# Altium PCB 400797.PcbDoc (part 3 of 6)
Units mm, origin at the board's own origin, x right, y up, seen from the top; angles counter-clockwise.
Board outline 155 x 63.5 mm, 4 copper layers (Top Layer, Mid-Layer 1, Mid-Layer 2, Bottom Layer), stack 1.514 mm thick; 317 components, 286 nets, 1519 pads, 2174 vias.
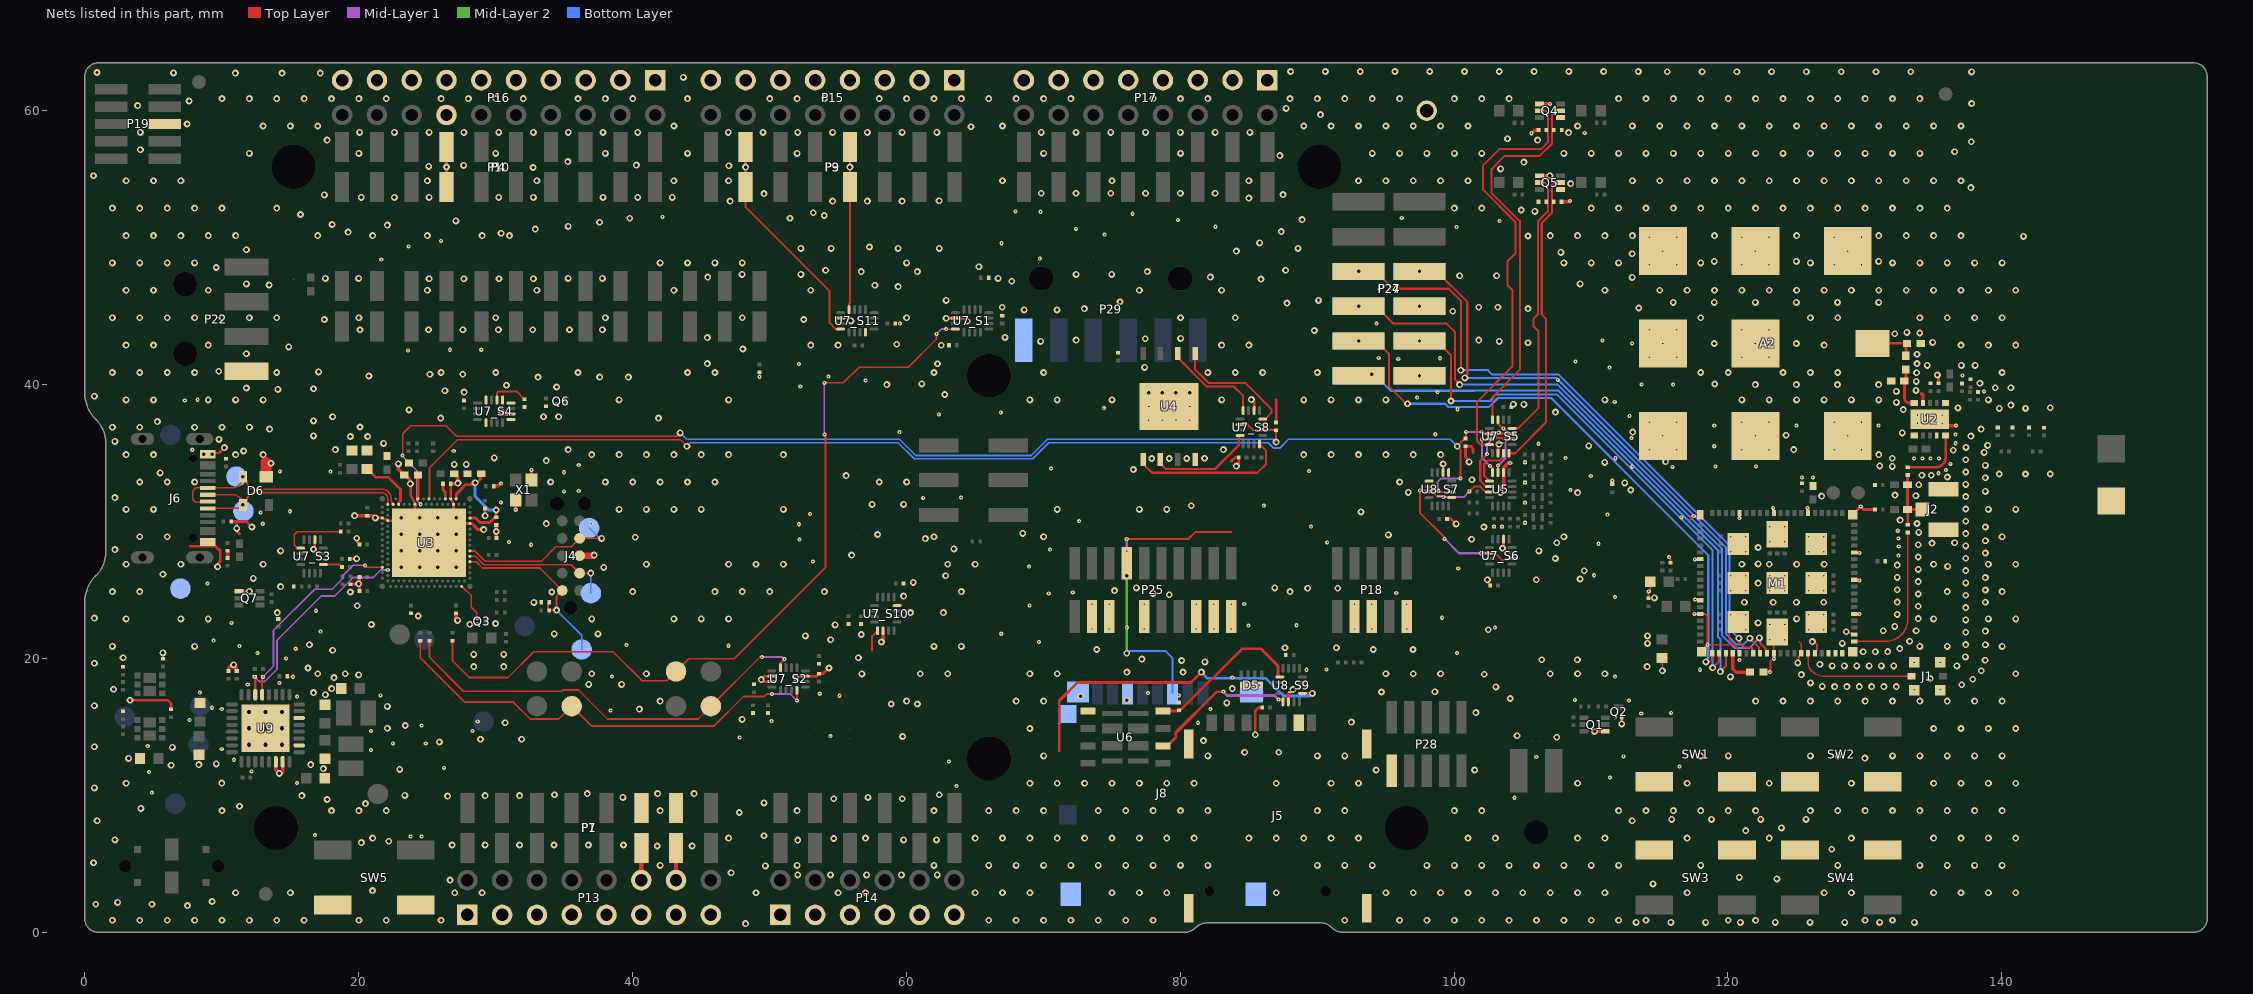
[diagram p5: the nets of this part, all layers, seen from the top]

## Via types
v1: diameter 0.5, hole 0.25, Top Layer to Bottom Layer, tented both sides, 1623 vias
v2: diameter 0.3, hole 0.1, Top Layer to Mid-Layer 1, tented top, 445 vias
v3: diameter 0.3, hole 0.1, Top Layer to Mid-Layer 1, tented both sides, 97 vias
v4: diameter 0.61, hole 0.305, Top Layer to Bottom Layer, tented both sides, 9 vias

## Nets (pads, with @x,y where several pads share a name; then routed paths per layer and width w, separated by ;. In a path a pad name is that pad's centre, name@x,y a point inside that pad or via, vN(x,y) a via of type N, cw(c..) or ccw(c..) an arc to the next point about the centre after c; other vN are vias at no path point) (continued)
COM.CH2_S2: R16.2 TP10.1 U7_S2.4 | length 31.8
  Top Layer w0.125: R16.2@25.175,21.299 25.175,20.088 27.651,17.613 34.83,17.613 34.915,17.698 36.052,17.698 36.748,17.002 36.748,16.999 38.174,15.573 44.782,15.573 TP10.1@45.72,16.51 49.31,20.1 v2(49.45,20.1)
  Top Layer w0.15: U7_S2.4@50.8,19.325 50.8,19.65 v2(51.1,19.95)
  Mid-Layer 1 w0.15: v2(49.45,20.1) 50.95,20.1 v2(51.1,19.95)
COM.CH2_S11: P3.4 P9.4 U7_S11.4 | length 15.4
  Top Layer w0.15: U7_S11.4@55.818,45.475 55.818,45.875 55.881,45.938 P3.4@55.88,54.416 P3.4@55.88,57.346
  Bottom Layer w0.15: P9.4@55.88,53.824 P9.4@55.88,54.416 v1(55.88,55.881) P9.4@55.88,57.346
COM.CH3_S1: R12.2 TP7.1 U7_S1.8 | length 59.3
  Top Layer w0.125: R12.2@26.85,21.299 26.85,19.827 28.065,18.613 30.903,18.613 32.778,20.488 38.573,20.488 40.698,18.363 42.492,18.363 TP7.1@43.18,19.05 44.118,19.988 47.423,19.988 54.1,26.664 54.1,36.263 v2(54.013,36.35) ; v2(54.013,40.125) 55.4,40.125 56.55,41.275 60.15,41.275 62.2,43.325 v2(62.2,43.7) ; v2(62.9,44.052) 62.902,44.05 U7_S1.8@63.575,44.05
  Mid-Layer 1 w0.125: v2(54.013,36.35) v2(54.013,40.125) ; v2@62.175,43.675 v2(62.2,43.7) 62.552,44.052 v2(62.9,44.052)
COM.CH3_S4: U7_S4.8
COM.CH3_S11: P3.7 P9.7 U7_S11.8 | length 19.9
  Top Layer w0.15: P3.7@48.26,57.346 48.26,52.962 54.393,46.829 54.393,44.504 54.846,44.05 U7_S11.8@55.193,44.05
  Bottom Layer w0.15: P9.7@48.26,53.849 P9.7@48.26,54.416 P9.7@48.26,57.346
  other v1: 48.26,55.881
COM.CH4_S2: R15.2 TP6.1 U7_S2.12 | length 33.5
  Top Layer w0.125: R15.2@24.5,21.299 24.5,20.056 27.744,16.813 31.302,16.813 32.542,15.573 34.622,15.573 TP6.1@35.56,16.51 36.998,15.073 45.962,15.073 48.107,17.218 49.621,17.218 49.804,17.4 v2(50.2,17.4)
  Top Layer w0.15: v2(52,16.925) U7_S2.12@52,17.675
  Mid-Layer 1 w0.125: v2(50.2,17.4) 51.525,17.4 v2(52,16.925)
COM.CH4_S4: U7_S4.12
COM.CH4_S10: U7_S10.12
COM.CH4_S11: U7_S11.12
D_N: D6.2 J6.A7 J6.B7 TP19.1 U3.B4 | length 18.2
  Top Layer w0.1: J6.A7@8.985,31.455 cw(c8.935,31.455) 8.935,31.405 8.2,31.405 cw(c8.2,31.705) 7.9,31.705 7.9,32.161 cw(c8.194,32.161) 8.194,32.455 J6.B7@8.985,32.455 10.738,32.455 ccw(c10.738,33.264) v1(11.547,33.259) ; D6.2@11.547,33.264 cw(c10.738,33.264) v1(11.547,33.259) ; U3.B4@22.525,31.264 22.525,31.314 22.375,31.464 22.375,31.664 ccw(c21.675,31.664) 21.675,32.364 12.397,32.364 cw(c12.397,32.914) 11.847,32.914 ccw(c11.497,32.914) v1(11.547,33.259)
D_P: D6.3 J6.A6 J6.B6 TP20.1 U3.B2 | length 17.4
  Top Layer w0.1: J6.B6@8.985,30.955 11.288,30.955 ccw(c11.288,31.214) 11.547,31.214 ccw(c10.805,31.214) D6.3@11.547,31.217 ; J6.A6@8.985,31.955 10.805,31.955 cw(c10.805,31.214) D6.3@11.547,31.217 ; U3.B2@22.125,31.264 22.125,31.664 ccw(c21.675,31.664) 21.675,32.114 12.397,32.114 ccw(c12.397,31.564) 11.847,31.564 cw(c11.497,31.564) D6.3@11.547,31.217
  other v1: 11.547,31.209
DBG_CMD: J8.3 P25.8 SB11.1 | length 20.5
  Top Layer w0.15: v2(76.095,28.72) 80.595,28.72 81.125,29.25 SB11.1@83.65,29.25 83.688,29.25
  Mid-Layer 1 w0.15: v2(76.095,27.85) v2(76.095,28.72)
  Mid-Layer 2 w0.15: v1(76.095,20.375) v1(76.095,26.05)
  Bottom Layer w0.15: v1(76.095,20.375) 76.27,20.55 78.9,20.55 79.45,20 J8.3@79.45,17.47
DEC0: C6.1 M1.24 | length 2.2
  Top Layer w0.254: M1.24@120.35,20.375 120.35,19.25 120.6,19 C6.1@121.35,19
DECA: C40.2 U3.A13 | length 1.9
  Top Layer w0.225: U3.A13@24.325,31.659 C40.2@24.325,33.389 C40.2@24.325,33.564
DECN: C39.1 U3.A23 | length 1.2
  Top Layer w0.2: C39.1@26.159,32.759 26.159,32.3 26.325,32.134 U3.A23@26.325,31.659
DECR: C29.2 C30.1 U3.A27 U3.G31 | length 8.6
  Top Layer w0.2: U3.A27@27.125,31.659 27.125,32.003 27.806,32.684 28.35,32.684 v1(28.5,32.834) ; U3.G31@28.125,30.259 28.55,30.259 28.875,29.934 29.575,29.934 30.046,30.405 v1(30.046,30.843) ; v1@28.55,32.759 28.9,33.109 C29.2@28.9,33.509
  Bottom Layer w0.2: v1(28.5,32.834) 28.5,31.846 29.504,30.843 v1(30.046,30.843)
DECUSB: C38.1 U3.B6 | length 4.2
  Top Layer w0.187: C38.1@20.625,33.834 20.655,33.834 21.246,33.243 22.158,33.243 23.056,32.345 23.056,31.522 22.932,31.398 22.932,31.266 U3.B6@22.925,31.259 ; C38.1@20.925,33.834 C38.1@20.925,33.839
EXT_MEM_C\S\: U4.1 U7_S8.16 | length 11.5
  Top Layer w0.15: U4.1@77.282,34.53 77.282,34.218 77.939,33.561 85.636,33.561 86.273,34.198 86.273,35.177 U7_S8.16@85.8,35.65
EXT_MEM_CTRL: R38.2 U3.B14 U7_S8.2 U7_S8.10 | length 75.1
  Top Layer w0.125: v2(23.212,34.809) 23.212,36.4 23.812,37 26.375,37 27.15,36.225 43.225,36.225 v1(43.475,36.475)
  Top Layer w0.15: U7_S8.10@84.375,37.075 84.925,37.075 85.325,36.675 U7_S8.2@86.025,36.675 86.989,36.675 R38.2@87.003,36.661 87.003,35.803 v1(87,35.8)
  Mid-Layer 1 w0.125: v2(23.212,34.809) 23.212,34.747 24.262,33.697 24.262,31.522 v2(24.525,31.259)
  Bottom Layer w0.125: v1(43.475,36.475) 43.942,36.009 59.495,36.009 60.679,34.825 69.121,34.825 70.305,36.009 86.792,36.009 v1(87,35.8)
EXT_MEM_MISO: U4.2 U7_S8.12 | length 7.7
  Top Layer w0.15: U4.2@78.552,34.53 78.552,34.223 78.939,33.836 82.536,33.836 84.29,35.59 84.29,36.275 U7_S8.12@84.375,36.275
EXT_MEM_MOSI: U4.5 U7_S8.4 | length 9
  Top Layer w0.15: U4.5@81.092,42.27 81.092,41.096 82.064,40.125 84.745,40.125 86.65,38.22 86.65,37.93 86.195,37.475 U7_S8.4@86.025,37.475
EXT_MEM_SCK: U4.6 U7_S8.8 | length 7.3
  Top Layer w0.15: U4.6@79.822,42.27 79.822,41.978 81.95,39.85 83.925,39.85 84.6,39.175 U7_S8.8@84.6,38.1
GND: A1.2 A2.2 C1.2 C2.2 C3.2 C4.2 C5.2 C6.2 C7.2 C10.2 C11.1 C14.1 C15.1 C16.1 C17.1 C18.2 C19.1 C21.1 C22.1 C23.1 C24.1 C25.1 C26.2 C27.1 C28.2 C29.1 C30.2 C31.1 C32.1 C33.1 C34.2 C35.1 C36.1 C37.2 C38.2 C39.2 C40.1 C41.1 C42.1 C43.1 C44.2 C45.1 C46.1 C47.1 C48.2 C49.1 C50.1 C51.1 C52_S1.2 C52_S2.2 C52_S3.2 C52_S4.2 C52_S5.2 C52_S6.2 C52_S8.2 C52_S10.2 C52_S11.2 C53_S7.2 C53_S9.2 C54.1 C55.1 C56.1 C57.1 C58.1 C59.1 C60.1 C62.2 D5.9 D6.1 J1.2 J2.2 J4.3 J5.0 J5.C5 J6.A1 J6.A12 J8.0 J8.6 J8.9 L2.1 L5.2 M1.1 M1.7 M1.13 M1.15 M1.20 M1.25 M1.30 M1.34 M1.36 M1.38 M1.39 M1.40 M1.41 M1.43 M1.46 M1.51 M1.55 M1.60 M1.66 M1.71 M1.76 M1.105 M1.106 M1.107 M1.108 M1.109 M1.110 M1.111 M1.112 M1.113 P1.6 P1.7 P4.7 P7.6 P7.7 P10.7 P13.1 P13.3 P13.5 P13.7 P13.9 P13.11 P13.12 P13.13 P13.14 P13.15 P14.1 P14.3 P14.5 P14.7 P14.9 P14.11 P15.1 P15.3 P15.5 P15.7 P15.9 P15.11 P15.13 P15.15 P16.1 P16.3 P16.5 P16.7 P16.9 P16.11 P16.13 P16.14 P16.15 P16.17 P16.19 P17.1 P17.3 P17.5 P17.7 P17.9 P17.11 P17.13 P17.15 P18.3 P18.5 P18.9 P19.5 P22.4 P24.8 P24.12 P25.3 P25.5 P25.9 P25.15 P25.17 P25.19 P27.8 P27.12 P28.1 P29.1 Q1.1 Q2.2 Q3.2 Q4.1 Q4.4 Q5.1 Q5.4 Q6.2 Q7.1 R3.1 R7.1 R13.2 R14.1 R17.2 R18.1 R24.1 R31.2 R32.1 R36.2 R37.2 R38.1 R43.1 R44.1 R45.1 R46.1 R47.1 R59.1 R65.1 R67.2 R68.1 R70.1 R71.1 R72.2 R73.1 R74.1 R76.2 R78.1 R80.2 R81.2 R85.2 R86.2 SB19.1 SW1.1 SW2.1 SW3.1 SW4.1 SW5.1 TP18.1 TP24.1 U2.1 U2.4 U2.6 U2.9 U2.11 U3.104 U3.A25 U3.B12 U3.B26 U3.G1 U3.H2 U3.J31 U4.4 U4.9 U5.6 U6.1 U7_S1.6 U7_S2.6 U7_S2.7 U7_S2.15 U7_S3.6 U7_S4.6 U7_S5.6 U7_S6.6 U7_S8.6 U7_S10.6 U7_S11.6 U8_S7.6 U8_S9.6 U9.2 U9.6 U9.30 U9.31 U9.33 X1.2 X1.4 | length 106.6
  Top Layer w0.125: C62.2@14.835,18.65 14.842,18.657 15.201,18.657 v2(15.208,18.664) ; C1.2@114.19,24.385 114.205,24.399 114.205,24.883 v3(114.219,24.898) 114.219,24.945 114.325,25.051 C7.2@114.325,25.6 ; C3.2@115.2,19.95 115.2,19.112 v1(115.213,19.1) ; v3(115.705,27.4) 115.705,27.352 115.8,27.257 C10.2@115.8,26.985 ; 117.2,30.1 117.3,30.2 117.3,30.4 v3(117.5,30.4) 117.875,30.4 M1.1@117.975,30.5 ; v2(117.55,23.25) M1.15@117.975,23.25 118.35,23.25 118.5,23.1 v3(118.5,21) 120.43,21 ; M1.107@120.75,22.65 120.65,22.65 120.1,22.1 120.1,21.33 120.43,21 ; M1.25@120.85,20.375 120.763,20.462 120.763,20.668 120.43,21 ; C6.2@122.85,19 123.114,19.264 123.114,19.814 123.336,20.036 123.336,20.361 M1.30@123.35,20.375 123.35,21.675 M1.108@123.6,21.925 ; v1(125.094,19.677) 125.158,19.74 125.158,20.042 125.188,20.072 125.188,20.139 125.261,20.212 125.263,20.212 125.35,20.3 M1.34@125.35,20.375 125.35,21.05 125.2,21.2 ; v1(126.17,21.233) 126.271,21.233 126.404,21.1 126.427,21.1 126.5,21.027 126.5,20.6 126.35,20.45 M1.36@126.35,20.375 ; v1(128.642,21.945) 128.744,21.945 128.87,21.818 129.157,21.818 M1.43@129.225,21.75
  Top Layer w0.15: v1(9.3,34.9) 9.295,34.905 J6.A1@8.985,34.905 9.08,35 9.8,35 v1(10.2,35.4) ; P4.7@26.416,54.416 P4.7@26.416,57.346 ; U8_S7.6@99.2,33.575 v1(99.2,34.2)
  Top Layer w0.165: U3.A25@26.725,31.659 U3.B26@26.925,31.259
  Top Layer w0.187: v1(21.225,30.259) U3.G1@21.725,30.259 U3.G1@21.725,30.259 cw(c21.634,30.095) U3.G1@21.766,30.228 ; U3.G1@21.766,30.228 21.775,30.22 ccw(c21.907,30.352) 21.907,30.165 21.957,30.165 cw(c21.956,29.978) U3.H2@22.125,30.059 U3.104@22.825,30.059 ; v1@23.8,32.863 23.8,31.972 23.8,31.929 23.819,31.89 U3.B12@24.125,31.259
  Top Layer w0.2: v1(3.3,16.95) 6.05,16.95 6.3,16.7 R81.2@6.3,16.285 ; 7.7,28.2 7.7,28.185 9.551,28.185 9.836,27.9 9.9,27.9 9.9,27.1 9.7,26.9 v1(9.7,26.7) ; R71.1@10.271,34.614 R71.1@10.3,34.585 ; R70.1@10.685,30 11.1,30 ; Q7.1@11.25,24.9 v1(12.025,24.9) ; 11.3,29.1 11.1,29.3 v1(11.1,29.5) 11.1,30 ; v1(12.2,29.6) 11.8,30 11.1,30 ; v1(16.7,27.975) 16.8,28.075 U7_S3.6@16.8,28.675 ; R24.1@19.36,27.275 v1(19.85,27.275) ; R65.1@19.4,25.415 v1@19.956,25.415 ; v1(20,25.459) 20.065,25.394 R31.2@20.065,24.925 ; v1@20.065,25.524 C26.2@20.065,25.959 ; U3.A25@26.725,31.659 C39.2@26.725,32.755 ; v1@28.075,22.5 v1(28.125,22.5) Q3.2@28.625,22.5 ; U7_S2.7@50.175,18.3 49.55,18.3 v1(49.4,18.45) 49.65,18.7 U7_S2.6@50.175,18.7 ; v1(51.925,18.6) 52.025,18.7 U7_S2.15@52.625,18.7 53.44,18.7 C52_S2.2@53.6,18.86 ; C52_S2.2@53.625,18.885 53.91,18.885 54.15,19.125 ; U7_S11.6@55.193,44.85 55.748,44.85 v1(55.948,44.65) ; 83.725,34.4 83.996,34.671 C52_S8.2@84.268,34.671 84.268,34.218 v1(84.1,34.05) ; v1(85.2,38.9) 85.4,38.7 U7_S8.6@85.4,38.1 ; v1(85.475,14.43) 85.475,16.175 85.725,16.425 C48.2@85.99,16.425 ; 87,38.883 87.003,38.881 R38.1@87.003,37.231 ; C53_S7.2@99.482,30.192 99.783,30.192 v1(100.15,29.825) ; 100.9,34.65 100.825,34.725 R47.1@100.825,35.49 101.236,35.49 101.388,35.338 101.388,35.038 ; v1(102.429,25.744) 102.486,25.686 102.486,25.501 102.638,25.349 C52_S6.2@102.638,25.334 ; U7_S5.6@103.21,34.984 103.21,35.575 v1(103.285,35.65) ; v1(103.535,28.043) 103.61,28.118 U7_S6.6@103.61,28.709 ; R46.1@106.16,53.35 R46.1@106.195,53.315 ; v1(112.24,15.221) Q2.2@112.24,15.75 ; v3(117.588,27.237) 117.595,27.243 117.968,27.243 M1.7@117.975,27.25 ; v3(117.6,24.3) 117.619,24.281 117.944,24.281 M1.13@117.975,24.25 ; M1.20@118.1,20.5 118.35,20.75 118.35,20.833 118.5,20.983 v3(118.5,21) ; v3(120.838,30.249) 120.844,30.255 120.844,30.619 M1.76@120.85,30.625 ; v3(123.3,31) 123.35,30.95 M1.71@123.35,30.625 ; v3(125.8,31) 125.85,30.95 M1.66@125.85,30.625 ; M1.60@129.1,30.5 v3(129.7,31.1) 129.92,30.88 C19.1@130.745,30.88 ; M1.46@129.225,23.25 v3(129.605,23.249) ; M1.51@129.225,25.75 129.256,25.719 129.581,25.719 v3(129.6,25.7) ; M1.55@129.225,27.75 129.55,27.75 v3(129.6,27.7)
  Top Layer w0.225: v1(19.864,28.779) 19.917,28.726 19.917,28.497 20.065,28.349 C25.1@20.065,28.334 ; U3.104@24.125,29.859 U3.B12@24.125,31.259 ; U3.B26@26.925,31.259 26.925,29.859 U3.J31@28.125,29.859 28.275,29.859 28.725,29.409 v1(29.125,29.409) ; v1@29.225,30.426 C33.1@29.225,30.949 ; C34.2@29.86,32.575 29.86,32.589 29.882,32.612 30.176,32.612 30.331,32.766 v2(30.405,32.766) ; C30.2@30.05,29.749 v1(30.05,29.272) 30.05,28.794 C32.1@30.06,28.784
  Top Layer w0.25: C51.1@10.425,27.335 C50.1@10.425,27.865 ; R36.2@10.5,19.085 10.515,19.085 10.525,19.095 10.525,19.325 10.8,19.6 v1(10.868,19.532) 11.075,19.325 11.075,19.095 11.085,19.085 R37.2@11.1,19.085 ; v1(14.2,11.6) 14.353,11.6 14.45,11.697 U9.31@14.45,12.45 ; v1(19.708,30.434) 19.713,30.429 20.6,30.429 C24.1@20.6,30.434 ; C24.1@20.625,30.424 20.65,30.414 20.995,30.414 cw(c20.994,30.164) v1(21.225,30.259) ; v1(22.9,34.209) 22.9,33.814 23.15,33.564 23.15,33.514 23.275,33.389 C40.1@23.325,33.389 ; C40.1@23.325,33.484 23.75,33.059 v1@23.75,32.909 ; C39.2@26.725,32.755 v1@27.196,32.755 ; C28.2@26.975,33.484 27.25,33.209 v1(27.25,32.809) ; C31.1@27.1,23.299 27.1,22.909 v1(27.229,22.779) ; v2(31.475,30.86) X1.4@31.475,31.588 ; X1.2@32.625,33.038 v2(32.625,33.767) ; R45.1@107.848,53.35 108.38,53.35 108.438,53.407 v2(108.465,53.407) ; v1(110.265,14.675) Q1.1@111.04,14.675 ; 134.125,39.347 134.247,39.225 U2.4@134.247,38.653 ; U2.11@134.747,37.465 v2(135.047,37.165) 135.204,37.008 v2(136.652,37.008) ; v1(135.3,40.697) 135.375,40.622 C15.1@135.375,40.107
  Top Layer w0.254: v1(30.4,38.05) 30.6,37.85 U7_S4.6@31.125,37.85 ; v1(58.175,21.2) 58.3,21.325 U7_S10.6@58.3,22.025 ; v1(62.9,44.848) 62.902,44.85 U7_S1.6@63.575,44.85 64.225,44.85 64.475,44.6 v1(64.45,44.625) ; U8_S9.6@87.9,16.825 87.9,17.4 v1(88.225,17.725) ; 103.4,32.475 103.61,32.685 U5.6@103.61,33.575 103.612,33.577 103.612,33.937 103.95,34.275 v2(104.1,34.275) ; R59.1@103.488,29.619 103.496,29.627 v2(103.511,29.627) ; v2(105.657,58.355) 105.88,58.577 106.163,58.577 106.171,58.585 R44.1@106.171,58.6 ; Q5.4@106.25,55.25 v1(107,55.25) ; Q4.4@106.25,60.5 v2(107,60.5)
  Top Layer w0.3: U9.30@13.95,12.45 13.95,11.85 v1(14.2,11.6) ; P13.12@40.64,3.811 P1.6@40.64,6.156 ; P13.14@43.18,3.811 P1.7@43.18,6.156
  Top Layer w0.5: J4.3@36.135,27.5 v1@37.15,27.5
  Top Layer w0.8: D6.1@13.247,33.259 13.247,34.297
  Mid-Layer 1 w0.2: v3@120.838,30.222 v3(120.838,30.249)
  Mid-Layer 1 w0.25: v4(14.4,13.7) v4@14.469,13.631 ; v1@17.568,17.343 v1(17.575,17.35)
  Bottom Layer w0.15: P10.7@26.416,54.416 P10.7@26.416,57.346
  other v1: 48.26,0.636 113.292,0.724 115.832,0.724 118.372,0.724 120.912,0.724 123.452,0.724 125.992,0.724 128.532,0.724 131.072,0.724 133.612,0.724 2.018,0.883 4.018,0.883 6.018,0.883 8.018,0.883 10.018,0.883 12.018,0.883 14.018,0.883 16.018,0.883 20.018,0.883 22.018,0.883 26.018,0.883 66.018,0.883 68.018,0.883 70.018,0.883 72.018,0.883 74.018,0.883 76.018,0.883 78.018,0.883 92.018,0.883 96.018,0.883 98.018,0.883 100.018,0.883 102.018,0.883 104.018,0.883 106.018,0.883 108.018,0.883 110.018,0.883 112.018,0.883 114.018,0.883 120.018,0.883 122.018,0.883 130.018,0.883 132.018,0.883 7.5,1.95 0.8,2.05 4.9,2.05 2.4,2.185 9.3,2.25 11.018,2.883 15.018,2.883 27.018,2.883 29.018,2.883 49.018,2.883 55.018,2.883 57.018,2.883 65.018,2.883 67.018,2.883 69.018,2.883 75.018,2.883 77.018,2.883 79.018,2.883 87.018,2.883 95.018,2.883 97.018,2.883 99.018,2.883 101.018,2.883 103.018,2.883 105.018,2.883 107.018,2.883 109.018,2.883 111.018,2.883 117.018,2.883 127.018,2.883 129.018,2.883 135.018,2.883 137.018,2.883 139.018,2.883 141.018,2.883 21.012,3.049 114.529,3.531 26.67,3.811 123.575,3.9 120.828,4.013 52.07,4.192 54.458,4.192 57.099,4.192 59.639,4.192 62.255,4.192 47.2,4.35 49.7,4.85 42.018,4.883 52.018,4.883 62.018,4.883 66.018,4.883 68.018,4.883 70.018,4.883 72.018,4.883 74.018,4.883 76.018,4.883 78.018,4.883 80.018,4.883 82.018,4.883 90.018,4.883 92.018,4.883 94.018,4.883 98.018,4.883 100.018,4.883 102.018,4.883 104.018,4.883 106.018,4.883 108.018,4.883 110.018,4.883 112.018,4.883 118.018,4.883 128.018,4.883 134.018,4.883 136.018,4.883 138.018,4.883 140.018,4.883 0.635,5.081 127.583,6.063 41.808,6.3 44.348,6.3 26.822,6.375 29.235,6.375 31.75,6.375 34.265,6.375 36.779,6.375 39.345,6.376 20.2,6.55 22.2,6.65 52.07,6.732 2.2,6.75 59.8,6.75 62.2,6.75 54.7,6.85 21.018,6.883 47.018,6.883 57.018,6.883 65.018,6.883 67.018,6.883 69.018,6.883 71.018,6.883 73.018,6.883 75.018,6.883 77.018,6.883 79.018,6.883 81.018,6.883 85.018,6.883 87.018,6.883 89.018,6.883 91.018,6.883 93.018,6.883 101.018,6.883 103.018,6.883 109.018,6.883 111.018,6.883 117.018,6.883 123.018,6.883 129.018,6.883 135.018,6.883 137.018,6.883 139.018,6.883 141.018,6.883 49.6,7.05 121.3,7.425 123.9,7.625 0.9,8.15 113,8.15 115.9,8.25 118.8,8.25 122.4,8.25 125.7,8.25 47.8,8.75 10.018,8.883 18.018,8.883 20.018,8.883 22.018,8.883 42.018,8.883 52.018,8.883 62.018,8.883 66.018,8.883 68.018,8.883 70.018,8.883 74.018,8.883 76.018,8.883 78.018,8.883 80.018,8.883 82.018,8.883 90.018,8.883 92.018,8.883 100.018,8.883 102.018,8.883 112.018,8.883 114.018,8.883 116.018,8.883 118.018,8.883 120.018,8.883 122.018,8.883 126.018,8.883 128.018,8.883 130.018,8.883 132.018,8.883 134.018,8.883 136.018,8.883 138.018,8.883 140.018,8.883 4.1,9.05 11.3,9.2 20.5,9.4 49.6,9.45 17.7,9.7 54.7,9.75 59.7,9.75 39.3,9.85 57.2,9.85 26.5,9.95 15.854,9.98 29.235,9.983 31.75,9.983 23.375,9.993 34.3,10.05 62.4,10.05 36.7,10.125 41.834,10.125 44.501,10.125 0.7,10.55 3.018,10.883 10,10.9 69.018,10.883 71.018,10.883 73.018,10.883 75.018,10.883 77.018,10.883 79.018,10.883 81.018,10.883 87.018,10.883 91.018,10.883 93.018,10.883 109.018,10.883 117.018,10.883 123.018,10.883 129.018,10.883 135.018,10.883 137.018,10.883 139.018,10.883 141.018,10.883 94.3,11.85 101.5,11.85 23,11.9 17.425,11.95 6.3,12.2 8.331,12.245 16.5,12.25 9.6,12.3 3.2,12.7 129.997,12.725 70.018,12.883 82.018,12.883 90.018,12.883 92.018,12.883 118.018,12.883 120.018,12.883 126.018,12.883 128.018,12.883 132.018,12.883 134.018,12.883 136.018,12.883 138.018,12.883 140.018,12.883 84.7,13.15 87.2,13.15 6.4,13.5 0.7,13.55 25.9,13.9 81.7,14 28.9,14.1 31.9,14.1 107.5,14.25 59.725,14.3 104.6,14.35 69.018,14.883 135.018,14.883 137.018,14.883 139.018,14.883 141.018,14.883 22.1,14.9 23.4,15.1 30.7,15.3 92.5,15.35 48,15.55 101.591,16.041 40.5,16.3 22.1,16.5 0.7,16.55 58.9,16.675 60.8,16.675 83.4,16.75 42.018,16.883 60.018,16.883 68.018,16.883 70.018,16.883 122.018,16.883 124.018,16.883 126.018,16.883 128.018,16.883 130.018,16.883 132.018,16.883 134.018,16.883 136.018,16.883 138.018,16.883 140.018,16.883 76.1,16.95 104.1,17.075 72.725,17.25 16.7,17.5 94.7,17.55 98.602,17.571 2.1,17.75 18.025,17.8 83.8,17.8 103.05,17.925 127.79,17.941 128.69,17.941 129.59,17.941 130.49,17.941 131.39,17.941 132.29,17.941 126.89,17.954 137.074,18.077 36.8,18.1 39.2,18.1 126.028,18.213 137.881,18.475 134.768,18.529 18.2,18.6 120.175,18.65 20,18.8 125.361,18.818 102.2,18.85 56.75,18.875 17.018,18.883 19.018,18.883 37.018,18.883 41.018,18.883 61.018,18.883 63.018,18.883 69.018,18.883 71.018,18.883 95.018,18.883 97.018,18.883 99.018,18.883 107.018,18.883 109.018,18.883 111.018,18.883 141.018,18.883 76.1,19 80.2,19 138.5,19.1 16.3,19.3 54.35,19.3 28.4,19.4 30.6,19.4 114.1,19.4 127.605,19.459 128.505,19.459 129.405,19.459 130.305,19.459 131.205,19.459 132.105,19.459 136.723,19.459 126.713,19.578 0.7,19.65 81.8,19.75 80.1,19.85 138.78,19.865 106.4,19.9 109,19.9 77.2,19.95 2.8,20.05 56.5,20.05 137.339,20.115 28.4,20.3 30.6,20.3 5.7,20.4 129.87,20.491 130.77,20.491 131.67,20.501 18.1,20.6 73.9,20.65 94.1,20.65 97,20.65 132.542,20.722 87.65,20.785 91.4,20.775 2.018,20.883 8.018,20.883 62.018,20.883 64.018,20.883 134.018,20.883 136.018,20.883 140.018,20.883 16.4,21 137.365,21.014 138.8,21 114.125,21.1 128.345,21.095 133.268,21.254 54.468,21.363 52.625,21.65 114.125,21.65 56.7,21.75 34.29,21.79 37.482,21.79 137.365,21.914 138.8,22 131.336,22.022 133.741,22.02 102.5,22.1 132.18,22.336 54.8,22.45 20.929,22.479 30,22.55 122.2,22.6 137.365,22.814 3.018,22.883 7.018,22.883 9.018,22.883 37.018,22.883 43.018,22.883 45.018,22.883 47.018,22.883 125.018,22.883 135.018,22.883 139.018,22.883 141.018,22.883 133.895,22.907 0.7,22.95 24.35,23.1 132.364,23.216 14.055,23.345 60.3,23.35 62.7,23.35 137.365,23.714 133.895,23.807 19.9,23.85 32.803,24.091 121.2,24.1 123.3,24.1 125,24.1 127,24.1 138.8,24.1 132.364,24.116 114.625,24.425 59.8,24.55 137.365,24.614 79.2,24.65 133.895,24.707 78,24.75 19.4,24.85 34.1,24.85 2.018,24.883 4.018,24.883 40.018,24.883 46.018,24.883 48.018,24.883 50.018,24.883 54.018,24.883 64.018,24.883 88.018,24.883 136.018,24.883 140.018,24.883 75.2,24.95 138.8,25 132.364,25.016 89.3,25.125 91.5,25.125 76.8,25.15 86.9,25.15 14.3,25.25 122.2,25.5 137.365,25.514 60.5,25.55 133.895,25.607 106,25.75 109.2,25.8 12.3,25.85 132.364,25.916 138.8,25.9 62.865,26.035 5.7,26.15 109.5,26.4 137.365,26.414 133.895,26.507 37.9,26.65 23.125,26.659 24.458,26.659 25.792,26.659 27.125,26.659 136.042,26.721 132.364,26.816 3.018,26.883 7.018,26.883 13.018,26.883 41.018,26.883 47.018,26.883 49.018,26.883 51.018,26.883 63.018,26.883 65.018,26.883 121.018,26.883 123.018,26.883 125.018,26.883 127.018,26.883 135.018,26.883 139.018,26.883 141.018,26.883 122.2,26.9 107.4,27.3 137.365,27.314 133.895,27.407 37.2,27.55 56,27.55 138.8,27.7 14.3,27.85 23.125,27.859 24.458,27.859 25.792,27.859 27.125,27.859 106.193,27.857 2.2,27.95 63.474,28.001 122.2,28.1 137.365,28.214 133.895,28.307 134.899,28.423 107.5,28.45 136.55,28.448 138.8,28.6 101.275,28.7 61.392,28.753 40.2,28.85 4.018,28.883 6.018,28.883 62.018,28.883 70.018,28.883 108.018,28.883 140.018,28.883 95.2,29.025 23.125,29.059 24.458,29.059 25.792,29.059 27.125,29.059 57.9,29.05 137.365,29.114 68.504,29.134 133.936,29.206 102.175,29.6 138.8,29.6 33.7,29.85 133.805,29.855 137.365,30.014 132.575,30.105 23.125,30.259 24.458,30.259 25.792,30.259 27.125,30.259 29.23,30.421 93.2,30.7 3.018,30.883 5.018,30.883 39.018,30.883 41.018,30.883 43.018,30.883 45.018,30.883 51.018,30.883 71.018,30.883 77.018,30.883 79.018,30.883 139.018,30.883 141.018,30.883 137.365,30.914 80.8,31.15 57.5,31.25 59.8,31.25 2.2,31.75 137.365,31.814 126.838,31.854 133.73,31.88 132.2,31.925 109.021,32.109 96.65,32.125 103.4,32.125 138.8,32.2 112.9,32.3 133.93,32.68 137.365,32.714 23.775,32.759 112.46,32.822 4.018,32.883 6.018,32.883 8.018,32.883 34.018,32.883 38.018,32.883 40.018,32.883 42.018,32.883 44.018,32.883 46.018,32.883 58.018,32.883 60.018,32.883 96.018,32.883 101.3,33.05 138.8,33.2 136.025,33.25 55.6,33.35 134.163,33.376 134.849,33.376 139.814,33.467 141.73,33.467 143.534,33.467 5.5,33.55 137.365,33.614 76.575,33.8 132,34.024 131.09,34.066 138.8,34.1 26.976,34.175 27.862,34.175 13.6,34.25 111,34.314 101.1,34.35 115.45,34.375 33.7,34.45 137.365,34.514 77.925,34.6 79.2,34.6 80.475,34.6 81.775,34.625 132,34.62 29.9,34.65 3.018,34.883 5.018,34.883 11.018,34.883 13.018,34.883 37.018,34.883 39.018,34.883 41.018,34.883 43.018,34.883 45.018,34.883 47.018,34.883 51.018,34.883 89.018,34.883 91.018,34.883 93.018,34.883 95.018,34.883 97.018,34.883 99.018,34.883 131.018,34.883 8.7,34.9 138.709,35.052 11.6,35.15 136.45,35.2 18.3,35.25 35.3,35.25 83.15,35.25 124.8,35.25 137.382,35.414 109.838,35.524 138.963,35.56 21.825,35.709 2.2,35.85 9.8,36 19.4,36.209 20.65,36.209 16.7,36.25 137.74,36.24 124.25,36.3 132.725,36.475 113.05,36.525 13.5,36.75 138.483,36.748 2.018,36.883 4.018,36.883 8.018,36.883 10.018,36.883 12.018,36.883 20.1,36.9 5.3,37.3 16.7,37.35 26,37.55 41.9,37.55 18.1,37.65 33.5,37.65 34.6,37.65 107.406,37.993 23.675,38.15 132.8,38.175 139.814,38.257 141.73,38.257 136.8,38.3 143.534,38.304 140.664,38.499 104.333,38.567 105.1,38.55 132.3,38.7 3.018,38.883 5.018,38.883 9.018,38.883 11.018,38.883 13.018,38.883 39.018,38.883 47.018,38.883 69.018,38.883 71.018,38.883 75.018,38.883 83.018,38.883 89.018,38.883 91.018,38.883 93.018,38.883 95.018,38.883 111.018,38.883 121.018,38.883 123.018,38.883 125.018,38.883 127.018,38.883 129.018,38.883 131.018,38.883 139.018,38.883 0.7,39.15 62.8,39.275 77.687,39.4 78.687,39.4 79.687,39.4 80.687,39.4 27.7,39.45 132.3,39.5 26.3,39.55 133.731,39.573 14.1,39.65 16.7,39.7 11.8,39.75 139.521,39.769 140.664,39.769 34.457,39.825 30.8,39.95 58.575,40 122,40 125,40 128,40 131,40 119.04,40.04 61.125,40.05 138.4,40.1 133.756,40.234 33.1,40.55 37.6,40.55 39.7,40.55 20.75,40.625 97.473,40.641 25.2,40.75 27.6,40.75 133.782,40.869 2.018,40.883 4.018,40.883 6.018,40.883 8.018,40.883 14.018,40.883 26.018,40.883 30.018,40.883 36.018,40.883 44.018,40.883 46.018,40.883 62.018,40.883 70.018,40.883 82.018,40.883 84.018,40.883 86.018,40.883 90.018,40.883 118.018,40.883 120.018,40.883 124.018,40.883 126.018,40.883 128.018,40.883 140.018,40.883 17.075,40.925 9.779,40.969 77.4,41.25 134.55,41.397 137.05,41.397 138.05,41.397 45.466,41.529 62.275,41.525 133.807,41.529 133.807,42.215 11.8,42.25 48.057,42.596 14.9,42.75 3.018,42.883 5.018,42.883 9.018,42.883 53.018,42.883 55.018,42.883 62.55,42.875 83.018,42.883 85.018,42.883 127.018,42.883 137.018,42.883 139.018,42.883 141.018,42.883 59.3,42.95 119,43 125,43 105.4,43.05 134.95,43.078 69.8,43.15 103.3,43.15 72.4,43.25 101.8,43.25 77.45,43.35 80.025,43.375 45.466,43.435 67.2,43.45 132.182,43.713 134.01,43.764 133.071,43.815 89.8,43.95 20.1,44 25.1,44 27.61,44 30.201,44 32.715,44 35.4,44 37.8,44 17.5,44.75 52.5,44.75 2.018,44.883 4.018,44.883 6.018,44.883 8.018,44.883 10.018,44.883 12.018,44.883 14.018,44.883 20.018,44.883 30.018,44.883 38.018,44.883 48.018,44.883 60.018,44.883 80.018,44.883 84.018,44.883 118.018,44.883 126.018,44.883 128.018,44.883 134.018,44.883 136.018,44.883 138.018,44.883 140.018,44.883 99.9,45.35 68.6,45.45 71,45.45 73,45.55 105.4,45.55 113.485,45.595 67,45.65 101.8,45.65 103.2,45.65 97.473,45.721 87.8,45.95 116,46 119,46 122,46 125,46 128,46 131,46 75.6,46.05 62.9,46.15 90.1,46.15 3.018,46.883 5.018,46.883 9.018,46.883 25.018,46.883 33.018,46.883 43.018,46.883 53.018,46.883 77.018,46.883 83.018,46.883 111.018,46.883 115.018,46.883 117.018,46.883 119.018,46.883 121.018,46.883 123.018,46.883 125.018,46.883 127.018,46.883 129.018,46.883 131.018,46.883 133.018,46.883 135.018,46.883 137.018,46.883 139.018,46.883 141.018,46.883 59.4,47.15 57.7,47.25 13.462,47.269 11.8,47.35 109.2,47.35 67.7,47.55 85.9,47.7 25.146,47.731 27.686,47.731 30.251,47.731 32.766,47.731 17.572,47.757 20,47.75 35.3,47.75 37.8,47.75 66.7,47.75 113,47.83 45.5,47.85 82.2,47.85 100.4,47.95 103.1,47.95 48,48.05 52.3,48.05 72.4,48.05 75,48.05 56.7,48.25 60.8,48.25 77.6,48.25 54.1,48.35 87.7,48.35 9.6,48.55 65.3,48.6 2.018,48.883 4.018,48.883 6.018,48.883 8.018,48.883 42.018,48.883 44.018,48.883 46.018,48.883 48.018,48.883 60.018,48.883 108.018,48.883 110.018,48.883 112.018,48.883 118.018,48.883 126.018,48.883 132.018,48.883 134.018,48.883 136.018,48.883 138.018,48.883 140.018,48.883 119,49 125,49 131,49 113,49.55 107.8,49.65 84.1,49.75 11.8,49.85 52.3,49.95 54.5,49.95 59.4,49.95 62.4,49.95 88.6,49.95 57.3,50.05 85.8,50.35 141.586,50.821 105.4,50.85 3.018,50.883 5.018,50.883 7.018,50.883 9.018,50.883 11.018,50.883 17.018,50.883 21.018,50.883 25.018,50.883 29.018,50.883 31.018,50.883 107.018,50.883 109.018,50.883 111.018,50.883 113.018,50.883 119.018,50.883 125.018,50.883 131.018,50.883 133.018,50.883 135.018,50.883 137.018,50.883 30.4,51.05 19.228,51.13 87.374,51.176 32.9,51.35 35.3,51.55 22.1,51.65 18.059,51.689 37.6,51.85 27.1,51.95 88.9,52.05 39.8,52.15 51.5,52.15 54,52.35 15.756,52.419 53.2,52.55 105.9,52.65 104.9,52.75 2.018,52.883 4.018,52.883 6.018,52.883 8.018,52.883 10.018,52.883 14.018,52.883 100.018,52.883 102.018,52.883 110.018,52.883 112.018,52.883 114.018,52.883 116.018,52.883 118.018,52.883 120.018,52.883 122.018,52.883 124.018,52.883 126.018,52.883 128.018,52.883 130.018,52.883 132.018,52.883 134.018,52.883 136.018,52.883 47.124,53.395 54.61,53.395 57.15,53.395 59.69,53.395 62.391,53.425 85.014,53.619 20.193,53.667 22.606,53.667 25.146,53.667 30.226,53.667 32.766,53.667 37.846,53.667 40.386,53.667 42.901,53.667 17.5,53.85 87.503,53.873 49.6,53.95 69.85,53.976 72.39,53.976 74.93,53.976 77.47,53.976 80.01,53.976 82.55,53.976 137.744,54.381 108.512,54.682 3.018,54.883 5.018,54.883 7.018,54.883 25.018,54.883 33.018,54.883 43.018,54.883 47.018,54.883 67.018,54.883 75.018,54.883 85.018,54.883 93.018,54.883 95.018,54.883 97.018,54.883 99.018,54.883 101.018,54.883 113.018,54.883 115.018,54.883 117.018,54.883 119.018,54.883 121.018,54.883 123.018,54.883 125.018,54.883 127.018,54.883 129.018,54.883 131.018,54.883 133.018,54.883 135.018,54.883 137.018,54.883 0.635,55.246 103.4,55.75 32.741,55.855 26.416,55.891 25.121,55.931 47.041,55.982 27.661,56.007 40.284,56.032 105.1,56.25 35.281,56.286 87.274,56.718 12.018,56.883 20.018,56.883 30.018,56.883 38.018,56.883 44.018,56.883 52.018,56.883 70.018,56.883 80.018,56.883 94.018,56.883 96.018,56.883 98.018,56.883 100.018,56.883 102.018,56.883 108.018,56.883 110.018,56.883 112.018,56.883 114.018,56.883 116.018,56.883 118.018,56.883 120.018,56.883 122.018,56.883 124.018,56.883 126.018,56.883 128.018,56.883 130.018,56.883 132.018,56.883 134.018,56.883 136.55,57 4.064,57.151 137.77,57.734 17.7,57.85 106.1,57.85 103.9,57.95 108.367,58.4 4.064,58.421 20.066,58.421 22.606,58.421 25.146,58.421 27.686,58.421 30.226,58.421 32.766,58.421 35.306,58.421 37.846,58.421 40.386,58.421 46.99,58.421 49.53,58.421 52.07,58.421 54.61,58.421 57.15,58.421 59.69,58.421 62.23,58.421 69.85,58.421 72.39,58.421 74.93,58.421 77.47,58.421 80.01,58.421 82.55,58.421 85.09,58.421 64.719,58.826 13.018,58.883 15.018,58.883 17.018,58.883 43.018,58.883 67.018,58.883 89.018,58.883 91.018,58.883 93.018,58.883 95.018,58.883 97.018,58.883 99.018,58.883 101.018,58.883 109.018,58.883 113.018,58.883 115.018,58.883 117.018,58.883 119.018,58.883 121.018,58.883 123.018,58.883 125.018,58.883 127.018,58.883 129.018,58.883 131.018,58.883 133.018,58.883 135.018,58.883 137.018,58.883 7.467,59.031 90.246,59.715 87.732,60.173 3.861,60.377 137.795,60.528 7.62,60.707 10.018,60.883 12.018,60.883 14.018,60.883 16.018,60.883 18.018,60.883 20.018,60.883 22.018,60.883 26.018,60.883 28.018,60.883 30.018,60.883 32.018,60.883 36.018,60.883 38.018,60.883 40.018,60.883 44.018,60.883 50.018,60.883 52.018,60.883 54.018,60.883 58.018,60.883 60.018,60.883 62.018,60.883 64.018,60.883 66.018,60.883 68.018,60.883 70.018,60.883 72.018,60.883 78.018,60.883 80.018,60.883 82.018,60.883 88.018,60.883 90.018,60.883 92.018,60.883 94.018,60.883 96.018,60.883 100.018,60.883 102.018,60.883 104.018,60.883 112.018,60.883 114.018,60.883 116.018,60.883 118.018,60.883 120.018,60.883 122.018,60.883 124.018,60.883 126.018,60.883 128.018,60.883 130.018,60.883 132.018,60.883 134.018,60.883 43.713,62.434 6.477,62.764 11,62.75 14.4,62.75 17.2,62.75 0.889,62.79 115.57,62.841 118.11,62.841 120.65,62.841 123.19,62.841 125.73,62.841 128.27,62.841 130.81,62.841 133.35,62.841 137.795,62.84 88.061,62.864 90.601,62.864 93.141,62.864 95.681,62.864 98.221,62.864 100.761,62.864 103.301,62.864 105.841,62.864 108.381,62.864 110.921,62.864 113.461,62.864
  other v2: 23.8,7 24.6,7 16.8,7.1 4.9,10.2 63.65,10.675 15.5,10.9 4.7,11.7 12.181,11.756 26.227,12.013 63.1,12.475 10.9,12.6 20.9,13.3 10,13.4 4.6,13.6 22.5,13.8 24.9,13.8 47.825,14.225 54.45,14.325 20.9,14.7 28.3,14.7 24.6,15.1 81.3,15.3 28.7,15.4 50.15,15.425 7.661,15.508 38.4,16.2 10,16.3 82.2,16.3 9.3,16.4 15.507,17.207 55.125,17.275 21.6,17.3 79.9,17.3 53.675,17.425 77.65,17.47 8.4,17.5 133.6,17.7 135.5,17.7 84.6,18.05 85.2,18.05 85.8,18.05 11.9,18.1 14.207,18.207 83.8,18.6 38.514,18.672 133.6,19.7 135.5,19.7 14.707,20.007 12.6,20.4 100.225,20.4 15.407,20.707 11.3,20.9 47,20.925 39.575,20.975 69.675,21.2 9.4,21.3 66.925,21.8 17.214,21.953 73.555,22.15 74.825,22.15 77.365,22.15 81.175,22.15 82.445,22.15 83.715,22.15 92.73,22.15 94,22.15 96.54,22.15 76.1,22.25 102.975,22.25 84.975,22.4 88.5,22.425 10.7,22.6 99.125,22.975 16.872,23.483 69,23.875 73.555,23.95 74.825,23.95 77.365,23.95 81.175,23.95 82.445,23.95 83.715,23.95 92.73,23.95 94,23.95 96.54,23.95 70.4,24.75 95.775,24.775 72.15,24.825 8.97,25.463 110.225,26.075 100.3,26.575 68.953,26.708 53.175,27.075 70.5,27.95 32.6,28.3 110.55,28.375 30.975,28.5 52.2,28.675 102.927,29.627 52.15,29.8 37,29.825 12.995,29.838 105.174,29.906 72.612,30.027 111.2,30.5 52.975,30.55 12.845,30.663 14.975,30.75 105.174,31.379 30.387,31.395 61.225,31.725 64,31.75 35,32.2 36.075,32.225 108.5,32.3 105.174,32.852 111.55,32.975 125.4,33.225 126.2,33.225 109.982,33.325 135.382,33.528 35,33.6 17.945,33.638 14.245,33.663 135.916,33.759 115.937,33.987 113,34 119.077,34.03 122.047,34.027 36.074,34.119 136.246,34.214 105.174,34.326 133.6,34.6 134.2,34.6 134.8,34.6 135.4,34.6 108.15,34.625 111.785,34.62 26.945,35.138 7.845,35.238 114.25,35.25 116.25,35.25 121,35.25 123,35.25 127.75,35.25 129.75,35.25 119,35.5 106.175,35.675 136.627,35.712 112.947,36.092 115.25,36.25 122,36.25 128.75,36.25 136.627,36.347 98.625,36.375 119,37 125,37 131,37 133.847,37.165 134.447,37.165 135.647,37.165 114.25,37.25 116.25,37.25 121,37.25 123,37.25 127.75,37.25 129.75,37.25 77.687,37.4 78.687,37.4 79.687,37.4 80.687,37.4 112.81,37.714 133.847,37.765 134.447,37.765 135.047,37.765 135.647,37.765 100.25,38.2 74.422,38.278 77.687,38.4 78.687,38.4 79.687,38.4 80.687,38.4 111.735,38.735 7.303,38.837 8.242,38.888 97.3,39.05 98.8,39.45 138.7,39.497 113.699,40.015 116,40 107.58,40.343 137.125,40.672 111.345,41.241 108.864,41.681 95.925,41.875 98.975,41.925 94.5,41.95 114.25,42 116.25,42 121,42 123,42 23.6,42.5 26.67,42.546 28.956,42.546 113,43 115.25,43 122,43 110.846,43.231 114.25,44 116.25,44 121,44 123,44 94.325,44.45 94.55,46.975 114.25,48.75 116.25,48.75 121,48.75 123,48.75 127.75,48.75 129.75,48.75 21.65,49.125 69.75,49.2 115.25,49.75 122,49.75 128.75,49.75 23.647,50.089 66.95,50.325 26.01,50.495 114.25,50.75 116.25,50.75 121,50.75 123,50.75 127.75,50.75 129.75,50.75 74.475,50.95 72.4,51.375 100.175,51.5 82.575,51.525 103.325,51.95 79.825,52.025 96.175,52.175 42.189,52.248 76.525,52.475 69.8,52.625 67.975,52.65 109.544,58.38
  other v3: 104.425,9.825 111.375,11.3 116.475,12.1 106,12.8 112.375,12.85 113.67,15.975 115.85,16.025 112.775,16.925 108.825,16.975 111.75,18.675 123.075,19 89.225,19.175 117.95,19.175 90.675,19.2 120.85,19.875 123.35,19.975 123.05,21.375 124.15,21.375 121.3,22.1 125.9,22.1 127,22.1 123.05,22.475 124.15,22.475 120.2,23.2 121.3,23.2 125.9,23.2 127,23.2 84.675,23.975 111.75,24.475 120.2,24.95 121.3,24.95 123.05,24.95 124.15,24.95 125.9,24.95 127,24.95 120.2,26.05 121.3,26.05 123.05,26.05 124.15,26.05 125.9,26.05 127,26.05 132.455,27.504 120.2,27.8 121.3,27.8 125.9,27.8 127,27.8 132.473,28.173 90.725,28.475 123.05,28.525 124.15,28.525 132.443,28.759 120.2,28.9 121.3,28.9 125.9,28.9 127,28.9 132.402,29.322 89.55,29.625 123.05,29.625 124.15,29.625 116.6,30.3 86.108,31.159 89.4,33.675 70.575,33.875 59.498,36.525 62.375,37.825 66.9,37.975 52.25,39.85 57.025,40.3 49.275,40.575 54.308,40.584 52.15,41.5 59.525,44.45
  other v4: 12,13.7 13.2,13.7 12,14.9 13.2,14.9 14.4,14.9 12,16.1 13.2,16.1 14.4,16.1
GPS_RF1: C12.2 M1.42 | length 11.2
  Top Layer w0.1: M1.42@129.225,21.25 129.231,21.256 131.536,21.256 ccw(c131.536,22.85) 133.13,22.85 133.13,28.131 ; 133.13,28.132 C12.2@133.13,29.195
GPS_RF2: C12.1 C13.2 J2.1 L3.2 L4.1 | length 4.7
  Top Layer w0.2: L4.1@133.105,30.88 L3.2@133.105,32.68 133.105,33.372 C13.2@133.13,33.397 ; C12.1@133.13,29.765 L4.1@133.13,30.855 ; L4.1@133.155,30.88 J2.1@134.205,30.88
GPS_RF3: C13.1 U2.10 | length 4.8
  Top Layer w0.2: C13.1@133.13,33.967 135.167,33.967 ccw(c135.167,34.7) 135.9,34.7 135.9,36.278 U2.10@135.891,36.278
GPS_RF4: L5.1 R4.1 U2.5 | length 3.1
  Top Layer w0.2: R4.1@133,41.1 133,40.375 cw(c132.875,40.375) L5.1@132.875,40.25 cw(c132.875,40.225) 132.9,40.225 132.9,39 ccw(c133.247,39) 133.247,38.653 U2.5@133.603,38.653
GPS_RF5: A2.1 C18.1 R4.2 | length 4
  Top Layer w0.191: A2.1@130.1,43 130.12,43.02 133.075,43.02 133.08,43.02 cw(c133.08,43) 133.1,43 ccw(c133.1,42.9) 133,42.9 R4.2@133,42.1 R4.2@133,42.075
IMCU_LED: Q3.1 U3.AL29 | length 2.8
  Top Layer w0.125: U3.AL29@27.525,25.235 27.578,25.235 28.221,24.592 28.221,23.729 28.625,23.325 Q3.1@28.625,22.95
IMCU_RESET: C41.2 J4.10 R34.1 TP14.1 U3.AC31 | length 14.1
  Top Layer w0.125: U3.AC31@28.125,27.059 28.585,27.059 29.044,26.6 33.225,26.6 J4.10@34.865,24.96 34.45,24.545 v1(34.45,23.525) 33.86,23.525 33.835,23.5 C41.2@33.835,24.1
  Bottom Layer w0.125: v1(34.45,23.525) 36.283,21.692 TP14.1@36.283,20.65
IMCU_SCL: R84.1 U3.AF2 U9.14 | length 15.8
  Top Layer w0.15: v2(12.412,18.657) 12.45,18.619 U9.14@12.45,17.35
  Mid-Layer 1 w0.125: v2(12.412,18.657) 12.749,18.32 13.152,18.32 14.034,19.202 14.034,21.334 17.262,24.562 18.261,24.562 19.611,25.913 21.076,25.913 21.622,26.459 v2(22.125,26.459)
IMCU_SDA: R83.1 U3.AE1 U9.13 | length 15.2
  Top Layer w0.125: v2(20.475,26.775) 20.6,26.65 21.709,26.65 21.712,26.647 U3.AE1@21.725,26.659
  Top Layer w0.15: U9.13@12.95,17.35 12.95,18.597 v2(13.012,18.657) v2(13.012,18.657)
  Mid-Layer 1 w0.125: v2(13.012,18.657) 13.784,19.429 13.784,22.061 16.785,25.063 18.054,25.063 18.832,25.841 18.832,26.034 19.61,26.813 20.39,26.813 20.428,26.775 v2(20.475,26.775)
IMCU_SWDCLK: J4.4 TP15.1 U3.W31 | length 11.9
  Top Layer w0.125: U3.W31@28.125,27.859 28.144,27.84 28.511,27.84 29.251,27.1 33.35,27.1 34.4,28.15 35.515,28.15 J4.4@36.135,28.77 v1(37.745,28.77)
  Bottom Layer w0.125: TP15.1@36.83,29.529 37.589,28.77 v1(37.745,28.77)
IMCU_SWDIO: J4.2 TP13.1 U3.AA31 | length 10.8
  Top Layer w0.125: U3.AA31@28.125,27.459 28.538,27.459 29.147,26.85 35.515,26.85 J4.2@36.135,26.23 v1(36.945,26.23)
  Bottom Layer w0.125: v1(36.945,26.23) 36.945,24.778 TP13.1@36.957,24.766
"IN 3-4_S4": R32.2 U7_S4.10 | length 2.8
  Top Layer w0.125: U7_S4.10@30.1,38.875 30.1,39.4 30.2,39.5 31.535,39.5 R32.2@32.1,38.935
INT_EXT: R50.1 U5.11 U8_S7.11 | length 4.8
  Top Layer w0.15: U8_S7.11@98.428,32.15 98.799,31.78 v2(99.215,31.78) ; v2(101.118,32.198) 101.47,32.549 ; 101.47,32.55 101.91,32.55 102.31,32.15 U5.11@102.585,32.15
  Mid-Layer 1 w0.15: v2(99.215,31.78) 100.7,31.78 v2(101.118,32.198)
IOEXP_CTRL: R47.2 U3.A17 U7_S5.2 U7_S5.10 U7_S6.2 U7_S6.10 U8_S7.2 | length 102.2
  Top Layer w0.125: U3.A17@25.125,31.659 25.125,31.686 25.175,31.736 25.175,33.934 27.216,35.975 43.5,35.975 v1(43.975,35.5)
  Top Layer w0.152: v2(97.5,32.275) 97.5,30.645 99.28,28.866 99.28,28.761 v2(99.308,28.733) ; v2(98.875,32.25) 98.975,32.15 U8_S7.2@99.825,32.15 ; v2(100.475,33.15) 100.475,35.25 v1(100.225,35.5) 100.785,36.06 R47.2@100.825,36.06 100.875,36.11 v2(100.875,36.55) ; v2(101.966,27.684) U7_S6.10@102.585,27.684 102.997,27.684 103.505,27.176 103.872,27.176 103.979,27.284 U7_S6.2@104.235,27.284 ; v2(102.05,36.55) 102.191,36.409 U7_S5.2@102.585,36.409 102.84,36.409 103.147,36.101 103.517,36.101 103.61,36.009 U7_S5.10@104.235,36.009
  Mid-Layer 1 w0.152: v2(97.5,32.275) v2@98.85,32.275 ; v2@98.864,32.239 v2(98.875,32.25) v2@98.85,32.275 ; v2(99.308,28.733) 100.357,27.684 v2(101.966,27.684) ; v2(100.475,33.15) 99.053,33.15 98.799,32.895 98.799,32.326 v2@98.85,32.275 ; v2(100.875,36.55) v2(102.05,36.55)
  Bottom Layer w0.125: v1(43.975,35.5) 44.233,35.759 59.392,35.759 60.575,34.575 69.225,34.575 70.408,35.759 86.423,35.759 86.819,35.362 87.263,35.362 87.909,36.009 99.717,36.009 v1(100.225,35.5)
LED1: Q4.2 R43.2 U7_S5.16 | length 28
  Top Layer w0.15: U7_S5.16@102.81,37.434 102.81,39.093 104.81,41.093 104.81,51.929 102.72,54.018 102.72,55.707 103.714,56.7 106.25,56.7 107.149,57.599 107.149,59.657 107.392,59.9 107.65,59.9 Q4.2@107.75,60
LED1_EXT: U5.7 U7_S5.15 | length 4.4
  Top Layer w0.15: U5.7@103.21,33.575 v2(103.21,34.086) ; U7_S5.15@103.21,37.434 103.21,37.125 103.535,36.8 v2(103.61,36.8)
  Mid-Layer 1 w0.15: v2(103.21,34.086) 103.76,34.636 103.76,36.65 v2(103.61,36.8)
LED2: Q4.5 R44.2 U7_S5.4 | length 31.9
  Top Layer w0.15: U7_S5.4@102.585,35.609 101.931,35.609 101.685,35.855 101.685,38.746 104.26,41.321 104.26,46.907 103.9,47.267 103.9,49 104.475,49.575 104.475,51.875 102.125,54.225 102.125,56.014 103.311,57.2 106.361,57.2 106.851,57.69 106.851,59.804 106.655,60 106.25,60 Q4.5@106.349,59.901
LED2_EXT: U5.8 U7_S5.3 | length 3.3
  Top Layer w0.15: v2(102.035,36) 102.044,36.009 U7_S5.3@102.585,36.009 ; v2(102.635,34.05) 102.81,33.875 U5.8@102.81,33.575
  Mid-Layer 1 w0.15: v2(102.035,36) 102.035,34.65 v2(102.635,34.05)
LED3: Q5.2 R45.2 U7_S5.8 | length 22.1
  Top Layer w0.15: U7_S5.8@104.01,34.984 104.459,34.984 106.704,37.229 106.704,44.821 106.402,45.123 106.402,51.802 107.149,52.549 107.149,54.554 107.345,54.75 Q5.2@107.75,54.75
LED3_EXT: U5.9 U7_S5.7 | length 3.3
  Top Layer w0.15: U5.9@102.585,32.95 102.201,33.333 102.201,34.192 102.469,34.459 103.344,34.459 103.61,34.725 U7_S5.7@103.61,34.984
LED4: Q5.5 R46.2 U7_S5.12 | length 20.2
  Top Layer w0.15: U7_S5.12@104.235,36.809 104.684,36.809 106.154,38.279 106.154,43.912 105.802,44.264 105.802,44.328 105.801,44.329 105.801,44.801 106.125,45.125 106.125,51.917 106.851,52.644 106.851,54.554 106.655,54.75 106.25,54.75 Q5.5@106.349,54.651
LED4_EXT: U5.10 U7_S5.11 | length 5.9
  Top Layer w0.15: v2(102.41,34.925) 101.91,34.425 101.91,32.972 102.331,32.55 U5.10@102.585,32.55 ; v2(103.26,36.5) 103.351,36.409 U7_S5.11@104.235,36.409
  Mid-Layer 1 w0.15: v2(102.41,34.925) 102.41,35.65 v2(103.26,36.5)
LTE_RF1: J1.1 M1.35 | length 8.7
  Top Layer w0.1: M1.35@125.85,20.375 125.85,19.703 ccw(c126.703,19.703) 126.1,19.1 ccw(c127.066,20.066) 127.066,18.7 J1.1@133.394,18.7
MAGPIO0: M1.21 P24.9 P27.9 | length 42.8
  Top Layer w0.15: v1(93.028,43.181) 94.294,43.181 95.25,42.225 95.25,39.85 96.364,38.736 96.369,38.736 96.505,38.6 v1(96.6,38.6) ; v1(118.387,19.75) 118.442,19.805 118.705,19.805 118.884,19.984 118.884,20.341 M1.21@118.85,20.375
  Bottom Layer w0.15: v1(96.6,38.6) 99.339,38.6 99.589,38.35 102.539,38.35 103.205,39.017 107.089,39.017 111.53,34.575 111.536,34.575 111.8,34.311 111.8,34.305 118.563,27.543 118.563,20.02 118.387,19.845 v1(118.387,19.75)
MAGPIO1: M1.22 P24.10 P27.10 | length 39.9
  Top Layer w0.15: v1(97.473,43.181) 98.744,43.181 99.775,42.15 v1(99.775,38.8) ; v1(118.883,19.317) 119.35,19.785 M1.22@119.35,20.375
  Bottom Layer w0.15: v1(99.775,38.8) 102.6,38.8 103.091,39.292 107.497,39.292 118.883,27.906 v1(118.883,19.317)
MAGPIO2: M1.23 P24.11 P27.11 | length 42
  Top Layer w0.15: v1(119.444,19.042) 119.85,19.448 M1.23@119.85,20.375
  Bottom Layer w0.15: P27.11@93.028,40.641 94.298,40.641 95.389,39.55 101.492,39.55 101.508,39.567 107.611,39.567 119.275,27.903 119.275,21.586 119.444,21.417 v1(119.444,19.042)
  other v1: 94,40.75
MIPI_SCLK: M1.28 P24.6 P27.6 | length 44.2
  Top Layer w0.15: v1(97.473,48.261) 98.739,48.261 100.96,46.04 100.96,40.752 100.789,40.582 v1(100.789,40.489) ; v1(121.6,21.478) 121.6,21.466 121.929,21.136 122.275,20.79 122.275,20.45 M1.28@122.35,20.375
  Bottom Layer w0.15: v1(100.789,40.489) 100.803,40.475 107.481,40.475 119.85,28.106 119.85,21.789 120.614,21.025 121.147,21.025 v1(121.6,21.478)
MIPI_SDATA: M1.27 P24.5 P27.5 | length 47.2
  Top Layer w0.15: v1(93.028,48.261) 94.289,48.261 95.55,47 99.611,47 100.5,46.111 v1(100.5,41.05) ; v1(120.8,21.475) 120.848,21.427 120.848,21.152 121.2,20.8 121.687,20.8 121.775,20.712 121.775,20.45 M1.27@121.85,20.375
  Bottom Layer w0.15: v1(100.5,41.05) 102.464,41.05 102.764,40.75 107.595,40.75 120.125,28.22 120.125,22.15 v1(120.8,21.475)
MIPI_VIO: M1.29 P24.7 P27.7 | length 47
  Top Layer w0.15: v1(93.028,45.721) 94.304,45.721 95.575,44.45 99.45,44.45 100.05,43.85 100.05,40.386 100.4,40.036 v1(100.4,40) ; v1(122.3,21.5) 122.367,21.433 122.367,21.1 122.775,20.692 122.775,20.45 M1.29@122.85,20.375
  Bottom Layer w0.15: v1(100.4,40) 107.567,40 119.55,28.017 119.55,21.7 120.5,20.75 121.55,20.75 v1(122.3,21.5)
NC.CH1_S3: R22.2 U7_S3.1 | length 1.4
  Top Layer w0.15: U7_S3.1@17.425,26.85 18.624,26.85 R22.2@18.79,26.684
NC.CH1_S4: U7_S4.1
NC.CH1_S7: U8_S7.1
NC.CH1_S9: C49.2 U6.8 U8_S9.1 | length 11.7
  Top Layer w0.2: U6.8@78.75,16.155 79.955,16.155 84.5,20.7 85.915,20.7 87.146,19.469 87.146,18.779 U8_S9.1@87.275,18.65
NC.CH2_S4: U7_S4.5
NC.CH2_S7: U8_S7.5
NC.CH2_S9: U6.6 U8_S9.5 | length 11.1
  Top Layer w0.2: U6.6@78.75,13.615 79.05,13.615 79.675,14.24 79.675,14.575 82.675,17.575 v2(83.15,17.575) ; v2(87.175,17) 87.325,17 U8_S9.5@87.5,16.825 U8_S9.5@87.5,17.05
  Mid-Layer 1 w0.2: v2(83.15,17.575) 83.425,17.3 86.875,17.3 v2(87.175,17)
NC.CH2_S10: SB21.1 U7_S10.5 | length 1.6
  Top Layer w0.15: SB21.1@57.5,20.588 SB21.1@57.5,20.6 57.5,21.625 U7_S10.5@57.9,22.025
NC.CH3_S3: R20.2 U7_S3.9 | length 4.8
  Top Layer w0.125: U7_S3.9@15.775,28.05 15.55,28.05 15.3,28.3 15.3,29.044 15.515,29.259 R20.2@18.69,29.259
NC.CH3_S4: U7_S4.9
NC.CH3_S7: U8_S7.9
NC.CH3_S9: SB13.2 SB14.2 U8_S9.9 | length 24.5
  Top Layer w0.2: SB14.2@71.162,13.25 71.162,16.912 72.5,18.25 80.8,18.25 v1(81.55,19) ; U8_S9.9@88.925,17.45 v1(89.65,17.45)
  Bottom Layer w0.2: v1(81.55,19) 82,18.55 86.25,18.55 87.55,17.25 89.45,17.25 v1(89.65,17.45)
